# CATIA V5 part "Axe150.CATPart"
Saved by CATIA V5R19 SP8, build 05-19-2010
Part number: Axe150
Bounding box of the stored display mesh (mm): x 0 to 150, y -15 to 15, z -15 to 15
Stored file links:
  J:\Travail\2e année\IAO\Projet\Axe150.CATPart
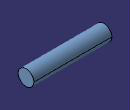
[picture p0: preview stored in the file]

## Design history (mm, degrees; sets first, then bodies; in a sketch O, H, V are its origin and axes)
Body1 (main body)
  Sketch1 on yz-plane, origin (0, 0, 0), H (0, 1, 0), V (0, 0, 1)
    circle A1 centre (0, 0) radius 15
    radius A1 = 15
  Pad1: profile Sketch1, direction (1, 0, 0), length 150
